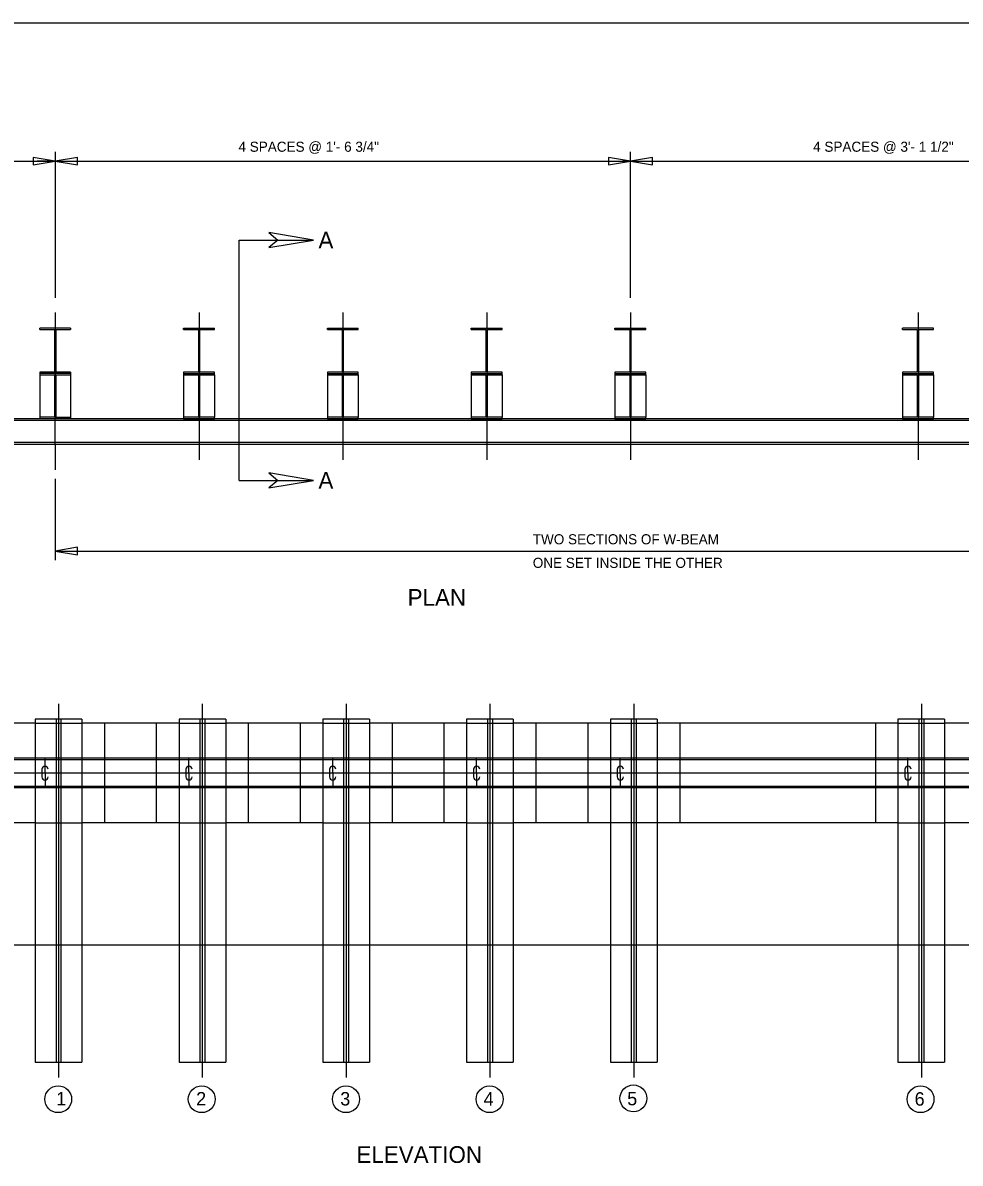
# Model space of a CAD drawing. Extents: x 809.7 to 842.4, y -901 to -880.3.
# Drawn here: x 819.41 to 829.59, y -892.79 to -880.4 of the extents above; entities that cross this region are included whole.
import ezdxf

# ---------------------------------------------------------------- set-up
doc = ezdxf.new("R2010")
doc.units = 0
for name, color, linetype in [('DIMENSION LINE', 7, 'Continuous'), ('EDGE OF PAVEMENT', 7, 'Continuous'), ('HIDDEN LINE', 7, 'Continuous'), ('OBJECT LINE', 7, 'Continuous'), ('REBAR', 7, 'Continuous'), ('STRUCTURES CENTERLINE', 7, 'Continuous'), ('STRUCTURES TEXT', 7, 'Continuous')]:
    doc.layers.add(name, color=color, linetype=linetype)

msp = doc.modelspace()

# ---------------------------------------------------------------- linework, layer by layer
at = {"layer": 'DIMENSION LINE'}
for p, q in [((819.76, -881.801), (819.76, -883.385)), ((826.01, -883.385), (826.01, -881.801)), ((813.51, -881.9), (819.76, -881.9)), ((819.76, -881.9), (826.01, -881.9)), ((826.01, -881.9), (832.26, -881.9)), ((819.76, -885.352), (819.76, -886.236)), ((819.76, -886.137), (832.26, -886.137)), ((819.616, -888.508), (819.616, -888.591)), ((821.179, -888.508), (821.179, -888.591)), ((822.741, -888.508), (822.741, -888.591)), ((824.304, -888.508), (824.304, -888.591)), ((825.866, -888.508), (825.866, -888.591)), ((828.991, -888.508), (828.991, -888.591))]:
    msp.add_line(p, q, dxfattribs=at)
for centre, start, end in [((819.65, -888.508), 360, 180), ((821.213, -888.508), 360, 180), ((822.775, -888.508), 360, 180), ((824.338, -888.508), 360, 180), ((825.9, -888.508), 360, 180), ((829.025, -888.508), 360, 180), ((819.65, -888.591), 180, 0), ((821.213, -888.591), 180, 0), ((822.775, -888.591), 180, 0), ((824.338, -888.591), 180, 0), ((825.9, -888.591), 180, 0), ((829.025, -888.591), 180, 0)]:
    msp.add_arc(centre, 0.0339, start, end, dxfattribs=at)
at = {"layer": 'EDGE OF PAVEMENT'}
for points in [[(819.52, -881.94), (819.76, -881.9), (819.52, -881.86)], [(820.001, -881.86), (819.76, -881.9), (820.001, -881.94)], [(825.77, -881.94), (826.01, -881.9), (825.77, -881.86)], [(826.251, -881.86), (826.01, -881.9), (826.251, -881.94)], [(820.001, -886.096), (819.76, -886.137), (820.001, -886.177)]]:
    msp.add_lwpolyline(points, close=True, dxfattribs=at)
for points in [[(819.76, -881.9), (819.564, -881.9)], [(819.76, -881.9), (819.872, -881.9)], [(826.01, -881.9), (825.927, -881.9)], [(826.046, -881.9), (826.041, -881.9)], [(826.046, -881.9), (826.12, -881.9)], [(819.76, -886.137), (819.867, -886.137)], [(819.76, -886.137), (819.822, -886.137)]]:
    msp.add_lwpolyline(points, dxfattribs=at)
for centre in [(819.792, -892.093), (821.352, -892.093), (822.919, -892.093), (824.48, -892.093), (826.042, -892.084), (829.162, -892.093)]:
    msp.add_circle(centre, 0.146, dxfattribs=at)
at = {"layer": 'HIDDEN LINE'}
for p, q in [((819.76, -884.978), (819.76, -884.701)), ((830.637, -884.958), (816.236, -884.958)), ((820.049, -887.964), (819.542, -887.964)), ((819.542, -887.964), (819.542, -890.417)), ((820.049, -887.964), (819.542, -887.964)), ((819.542, -887.964), (819.542, -890.417)), ((820.049, -887.964), (819.542, -887.964)), ((819.542, -887.964), (819.542, -890.417)), ((820.049, -887.964), (819.542, -887.964)), ((819.542, -887.964), (819.542, -890.417)), ((819.542, -888.006), (820.049, -888.006)), ((819.769, -887.964), (819.769, -891.69)), ((819.822, -887.964), (819.822, -891.69)), ((820.049, -887.964), (820.049, -890.417)), ((820.049, -887.964), (820.049, -890.417)), ((820.049, -887.964), (820.049, -890.417)), ((820.049, -887.964), (820.049, -890.417)), ((820.858, -888.006), (820.858, -889.089)), ((821.612, -887.964), (821.105, -887.964)), ((821.105, -887.964), (821.105, -890.417)), ((821.612, -887.964), (821.105, -887.964)), ((821.105, -887.964), (821.105, -890.417)), ((821.612, -887.964), (821.105, -887.964)), ((821.105, -887.964), (821.105, -890.417)), ((821.612, -887.964), (821.105, -887.964)), ((821.105, -887.964), (821.105, -890.417)), ((821.612, -887.964), (821.105, -887.964)), ((821.105, -887.964), (821.105, -890.417)), ((821.612, -887.964), (821.105, -887.964)), ((821.105, -887.964), (821.105, -890.417)), ((821.612, -887.964), (821.105, -887.964)), ((821.105, -887.964), (821.105, -890.417)), ((821.612, -887.964), (821.105, -887.964)), ((821.105, -887.964), (821.105, -890.417)), ((821.105, -888.006), (821.612, -888.006)), ((821.332, -887.964), (821.332, -891.69)), ((821.385, -887.964), (821.385, -891.69)), ((821.612, -887.964), (821.612, -890.417)), ((821.612, -887.964), (821.612, -890.417)), ((821.612, -887.964), (821.612, -890.417)), ((821.612, -887.964), (821.612, -890.417)), ((821.612, -887.964), (821.612, -890.417)), ((821.612, -887.964), (821.612, -890.417)), ((821.612, -887.964), (821.612, -890.417)), ((821.612, -887.964), (821.612, -890.417)), ((822.421, -888.006), (822.421, -889.089)), ((823.174, -887.964), (822.667, -887.964)), ((822.667, -887.964), (822.667, -890.417)), ((823.174, -887.964), (822.667, -887.964)), ((822.667, -887.964), (822.667, -890.417)), ((823.174, -887.964), (822.667, -887.964)), ((822.667, -887.964), (822.667, -890.417)), ((823.174, -887.964), (822.667, -887.964)), ((822.667, -887.964), (822.667, -890.417)), ((823.174, -887.964), (822.667, -887.964)), ((822.667, -887.964), (822.667, -890.417)), ((823.174, -887.964), (822.667, -887.964)), ((822.667, -887.964), (822.667, -890.417)), ((823.174, -887.964), (822.667, -887.964)), ((822.667, -887.964), (822.667, -890.417)), ((823.174, -887.964), (822.667, -887.964)), ((822.667, -887.964), (822.667, -890.417)), ((822.667, -888.006), (823.174, -888.006)), ((822.894, -887.964), (822.894, -891.69)), ((822.947, -887.964), (822.947, -891.69)), ((823.174, -887.964), (823.174, -890.417)), ((823.174, -887.964), (823.174, -890.417)), ((823.174, -887.964), (823.174, -890.417)), ((823.174, -887.964), (823.174, -890.417)), ((823.174, -887.964), (823.174, -890.417)), ((823.174, -887.964), (823.174, -890.417)), ((823.174, -887.964), (823.174, -890.417)), ((823.174, -887.964), (823.174, -890.417)), ((823.983, -888.006), (823.983, -889.089)), ((824.737, -887.964), (824.23, -887.964)), ((824.23, -887.964), (824.23, -890.417)), ((824.737, -887.964), (824.23, -887.964)), ((824.23, -887.964), (824.23, -890.417)), ((824.737, -887.964), (824.23, -887.964)), ((824.23, -887.964), (824.23, -890.417)), ((824.737, -887.964), (824.23, -887.964)), ((824.23, -887.964), (824.23, -890.417)), ((824.737, -887.964), (824.23, -887.964)), ((824.23, -887.964), (824.23, -890.417)), ((824.737, -887.964), (824.23, -887.964)), ((824.23, -887.964), (824.23, -890.417)), ((824.737, -887.964), (824.23, -887.964)), ((824.23, -887.964), (824.23, -890.417)), ((824.737, -887.964), (824.23, -887.964)), ((824.23, -887.964), (824.23, -890.417)), ((824.23, -888.006), (824.737, -888.006)), ((824.457, -887.964), (824.457, -891.69)), ((824.51, -887.964), (824.51, -891.69)), ((824.737, -887.964), (824.737, -890.417)), ((824.737, -887.964), (824.737, -890.417)), ((824.737, -887.964), (824.737, -890.417)), ((824.737, -887.964), (824.737, -890.417)), ((824.737, -887.964), (824.737, -890.417)), ((824.737, -887.964), (824.737, -890.417)), ((824.737, -887.964), (824.737, -890.417)), ((824.737, -887.964), (824.737, -890.417)), ((825.546, -888.006), (825.546, -889.089)), ((826.299, -887.964), (825.792, -887.964)), ((825.792, -887.964), (825.792, -890.417)), ((826.299, -887.964), (825.792, -887.964)), ((825.792, -887.964), (825.792, -890.417)), ((826.299, -887.964), (825.792, -887.964)), ((825.792, -887.964), (825.792, -890.417)), ((826.299, -887.964), (825.792, -887.964)), ((825.792, -887.964), (825.792, -890.417)), ((826.299, -887.964), (825.792, -887.964)), ((825.792, -887.964), (825.792, -890.417)), ((826.299, -887.964), (825.792, -887.964)), ((825.792, -887.964), (825.792, -890.417)), ((826.299, -887.964), (825.792, -887.964)), ((825.792, -887.964), (825.792, -890.417)), ((826.299, -887.964), (825.792, -887.964)), ((825.792, -887.964), (825.792, -890.417)), ((825.792, -888.006), (826.299, -888.006)), ((826.019, -887.964), (826.019, -891.69)), ((826.072, -887.964), (826.072, -891.69)), ((826.299, -887.964), (826.299, -890.417)), ((826.299, -887.964), (826.299, -890.417)), ((826.299, -887.964), (826.299, -890.417)), ((826.299, -887.964), (826.299, -890.417)), ((826.299, -887.964), (826.299, -890.417)), ((826.299, -887.964), (826.299, -890.417)), ((826.299, -887.964), (826.299, -890.417)), ((826.299, -887.964), (826.299, -890.417)), ((828.671, -888.006), (828.671, -889.089)), ((829.424, -887.964), (828.917, -887.964)), ((828.917, -887.964), (828.917, -890.417)), ((829.424, -887.964), (828.917, -887.964)), ((828.917, -887.964), (828.917, -890.417)), ((829.424, -887.964), (828.917, -887.964)), ((828.917, -887.964), (828.917, -890.417)), ((829.424, -887.964), (828.917, -887.964)), ((828.917, -887.964), (828.917, -890.417)), ((829.424, -887.964), (828.917, -887.964)), ((828.917, -887.964), (828.917, -890.417)), ((829.424, -887.964), (828.917, -887.964)), ((828.917, -887.964), (828.917, -890.417)), ((829.424, -887.964), (828.917, -887.964)), ((828.917, -887.964), (828.917, -890.417)), ((829.424, -887.964), (828.917, -887.964)), ((828.917, -887.964), (828.917, -890.417)), ((829.424, -887.964), (828.917, -887.964)), ((828.917, -887.964), (828.917, -890.417)), ((829.424, -887.964), (828.917, -887.964)), ((828.917, -887.964), (828.917, -890.417)), ((829.424, -887.964), (828.917, -887.964)), ((828.917, -887.964), (828.917, -890.417)), ((829.424, -887.964), (828.917, -887.964)), ((828.917, -887.964), (828.917, -890.417)), ((829.424, -887.964), (828.917, -887.964)), ((828.917, -887.964), (828.917, -890.417)), ((829.424, -887.964), (828.917, -887.964)), ((828.917, -887.964), (828.917, -890.417)), ((829.424, -887.964), (828.917, -887.964)), ((828.917, -887.964), (828.917, -890.417)), ((829.424, -887.964), (828.917, -887.964)), ((828.917, -887.964), (828.917, -890.417)), ((828.917, -888.006), (829.424, -888.006)), ((829.144, -887.964), (829.144, -891.69)), ((829.197, -887.964), (829.197, -891.69)), ((829.424, -887.964), (829.424, -890.417)), ((829.424, -887.964), (829.424, -890.417)), ((829.424, -887.964), (829.424, -890.417)), ((829.424, -887.964), (829.424, -890.417)), ((829.424, -887.964), (829.424, -890.417)), ((829.424, -887.964), (829.424, -890.417)), ((829.424, -887.964), (829.424, -890.417)), ((829.424, -887.964), (829.424, -890.417)), ((829.424, -887.964), (829.424, -890.417)), ((829.424, -887.964), (829.424, -890.417)), ((829.424, -887.964), (829.424, -890.417)), ((829.424, -887.964), (829.424, -890.417)), ((829.424, -887.964), (829.424, -890.417)), ((829.424, -887.964), (829.424, -890.417)), ((829.424, -887.964), (829.424, -890.417)), ((829.424, -887.964), (829.424, -890.417)), ((834.183, -888.389), (816.316, -888.389)), ((834.183, -888.404), (816.316, -888.404)), ((834.183, -888.694), (816.316, -888.694)), ((834.183, -888.71), (816.316, -888.71)), ((819.542, -889.089), (820.049, -889.089)), ((821.105, -889.089), (821.612, -889.089)), ((822.667, -889.089), (823.174, -889.089)), ((824.23, -889.089), (824.737, -889.089)), ((826.299, -889.089), (825.792, -889.089)), ((828.917, -889.089), (829.424, -889.089)), ((819.542, -890.417), (819.542, -891.69)), ((820.049, -890.417), (820.049, -891.69)), ((821.105, -890.417), (821.105, -891.69)), ((821.612, -890.417), (821.612, -891.69)), ((822.667, -890.417), (822.667, -891.69)), ((823.174, -890.417), (823.174, -891.69)), ((824.23, -890.417), (824.23, -891.69)), ((824.737, -890.417), (824.737, -891.69)), ((825.792, -890.417), (825.792, -891.69)), ((826.299, -890.417), (826.299, -891.69)), ((828.917, -890.417), (828.917, -891.69)), ((829.424, -890.417), (829.424, -891.69)), ((819.542, -891.69), (820.049, -891.69)), ((821.105, -891.69), (821.612, -891.69)), ((822.667, -891.69), (823.174, -891.69)), ((824.23, -891.69), (824.737, -891.69)), ((825.792, -891.69), (826.299, -891.69)), ((828.917, -891.69), (829.424, -891.69))]:
    msp.add_line(p, q, dxfattribs=at)
at = {"layer": 'OBJECT LINE'}
for p, q in [((819.594, -883.73), (819.594, -883.714)), ((819.927, -883.714), (819.927, -883.73)), ((821.155, -883.73), (821.155, -883.714)), ((821.155, -883.714), (821.49, -883.714)), ((822.717, -883.73), (822.717, -883.714)), ((822.717, -883.714), (823.053, -883.714)), ((824.28, -883.73), (824.28, -883.714)), ((824.28, -883.714), (824.615, -883.714)), ((824.615, -883.73), (824.615, -883.714)), ((825.842, -883.73), (825.842, -883.714)), ((825.842, -883.714), (826.178, -883.714)), ((826.178, -883.73), (826.178, -883.714)), ((828.967, -883.73), (828.967, -883.714)), ((819.594, -884.192), (819.594, -884.701)), ((819.927, -884.192), (819.927, -884.701)), ((821.155, -884.215), (821.155, -884.684)), ((821.49, -884.223), (821.49, -884.684)), ((822.717, -884.215), (822.717, -884.684)), ((823.053, -884.223), (823.053, -884.684)), ((824.28, -884.215), (824.28, -884.684)), ((824.615, -884.223), (824.615, -884.684)), ((825.842, -884.215), (825.842, -884.684)), ((826.178, -884.223), (826.178, -884.684)), ((828.967, -884.215), (828.967, -884.684)), ((829.303, -884.223), (829.303, -884.684)), ((830.637, -884.701), (816.236, -884.701)), ((822.502, -884.72), (816.236, -884.72)), ((819.769, -884.684), (819.927, -884.684)), ((821.155, -884.684), (821.155, -884.701)), ((830.637, -884.72), (822.502, -884.72)), ((822.717, -884.684), (822.717, -884.701)), ((824.28, -884.684), (824.28, -884.701)), ((825.842, -884.684), (825.842, -884.701)), ((828.967, -884.684), (828.967, -884.701)), ((830.683, -884.978), (816.236, -884.978)), ((819.542, -888.006), (816.316, -888.006)), ((821.105, -888.006), (820.049, -888.006)), ((820.296, -888.006), (820.296, -889.089)), ((822.667, -888.006), (821.612, -888.006)), ((821.858, -888.006), (821.858, -889.089)), ((824.23, -888.006), (823.174, -888.006)), ((823.421, -888.006), (823.421, -889.089)), ((825.792, -888.006), (824.737, -888.006)), ((824.983, -888.006), (824.983, -889.089)), ((828.917, -888.006), (826.299, -888.006)), ((826.546, -888.006), (826.546, -889.089)), ((830.657, -888.006), (829.424, -888.006)), ((819.542, -889.089), (816.316, -889.089)), ((821.105, -889.089), (820.049, -889.089)), ((822.667, -889.089), (821.612, -889.089)), ((824.23, -889.089), (823.174, -889.089)), ((825.792, -889.089), (824.737, -889.089)), ((828.917, -889.089), (826.299, -889.089)), ((830.637, -889.089), (829.424, -889.089)), ((816.316, -890.417), (830.637, -890.417))]:
    msp.add_line(p, q, dxfattribs=at)
for points in [[(819.927, -883.714), (819.594, -883.714)], [(819.594, -883.73), (819.752, -883.73)], [(819.752, -883.73), (819.752, -884.192), (819.594, -884.192)], [(819.769, -883.73), (819.927, -883.73)], [(819.927, -884.192), (819.769, -884.192), (819.769, -883.73)], [(821.155, -884.207), (821.49, -884.207), (821.49, -884.192), (821.331, -884.192), (821.331, -883.73)], [(821.315, -883.73), (821.315, -884.192), (821.155, -884.192), (821.155, -884.207)], [(821.155, -883.73), (821.315, -883.73)], [(821.331, -883.73), (821.49, -883.73), (821.49, -883.714)], [(822.717, -884.207), (823.053, -884.207), (823.053, -884.192), (822.894, -884.192), (822.894, -883.73)], [(822.877, -883.73), (822.877, -884.192), (822.717, -884.192), (822.717, -884.207)], [(822.717, -883.73), (822.877, -883.73)], [(822.894, -883.73), (823.053, -883.73), (823.053, -883.714)], [(824.28, -884.207), (824.615, -884.207), (824.615, -884.192), (824.456, -884.192), (824.456, -883.73)], [(824.28, -883.73), (824.44, -883.73)], [(824.456, -883.73), (824.615, -883.73)], [(825.842, -884.207), (826.178, -884.207), (826.178, -884.192), (826.019, -884.192), (826.019, -883.73)], [(826.002, -883.73), (826.002, -884.192), (825.842, -884.192), (825.842, -884.207)], [(825.842, -883.73), (826.002, -883.73)], [(826.019, -883.73), (826.178, -883.73)], [(829.144, -883.73), (829.303, -883.73), (829.303, -883.714), (828.967, -883.714)], [(829.127, -883.73), (829.127, -884.192), (828.967, -884.192), (828.967, -884.207)], [(828.967, -883.73), (829.127, -883.73)], [(828.967, -884.207), (829.303, -884.207), (829.303, -884.192), (829.144, -884.192), (829.144, -883.73)], [(819.927, -884.207), (819.594, -884.207)], [(819.594, -884.223), (819.752, -884.223), (819.752, -884.684)], [(819.769, -884.684), (819.769, -884.223), (819.927, -884.223)], [(821.155, -884.207), (821.155, -884.223), (821.315, -884.223), (821.315, -884.684)], [(821.331, -884.684), (821.331, -884.223), (821.49, -884.223), (821.49, -884.207)], [(822.717, -884.207), (822.717, -884.223), (822.877, -884.223), (822.877, -884.684)], [(822.894, -884.684), (822.894, -884.223), (823.053, -884.223), (823.053, -884.207)], [(824.28, -884.207), (824.28, -884.223), (824.44, -884.223), (824.44, -884.684)], [(824.456, -884.684), (824.456, -884.223), (824.615, -884.223), (824.615, -884.207)], [(825.842, -884.207), (825.842, -884.223), (826.002, -884.223), (826.002, -884.684)], [(826.019, -884.684), (826.019, -884.223), (826.178, -884.223), (826.178, -884.207)], [(828.967, -884.207), (828.967, -884.223), (829.127, -884.223), (829.127, -884.684)], [(829.144, -884.684), (829.144, -884.223), (829.303, -884.223), (829.303, -884.207)], [(819.752, -884.684), (819.594, -884.684)], [(821.155, -884.701), (821.49, -884.701), (821.49, -884.684), (821.331, -884.684)], [(821.315, -884.684), (821.155, -884.684)], [(822.717, -884.701), (823.053, -884.701), (823.053, -884.684), (822.894, -884.684)], [(822.877, -884.684), (822.717, -884.684)], [(824.28, -884.701), (824.615, -884.701), (824.615, -884.684), (824.456, -884.684)], [(824.44, -884.684), (824.28, -884.684)], [(825.842, -884.701), (826.178, -884.701), (826.178, -884.684), (826.019, -884.684)], [(826.002, -884.684), (825.842, -884.684)], [(828.967, -884.701), (829.303, -884.701), (829.303, -884.684), (829.144, -884.684)], [(829.127, -884.684), (828.967, -884.684)]]:
    msp.add_lwpolyline(points, dxfattribs=at)
at = {"layer": 'REBAR'}
msp.add_line((811.186, -880.398), (842.1, -880.399), dxfattribs=at)
at = {"layer": 'STRUCTURES CENTERLINE'}
for p, q in [((821.759, -882.758), (822.565, -882.758)), ((821.759, -885.369), (821.759, -882.758)), ((819.76, -883.547), (819.76, -884.701)), ((821.323, -883.547), (821.323, -885.145)), ((822.885, -883.547), (822.885, -885.145)), ((824.448, -883.547), (824.448, -885.145)), ((826.01, -883.547), (826.01, -885.145)), ((829.135, -883.547), (829.135, -885.145)), ((819.76, -884.978), (819.76, -885.253)), ((821.759, -885.369), (822.565, -885.369)), ((819.796, -887.797), (819.796, -891.857)), ((821.358, -887.797), (821.358, -891.857)), ((822.921, -887.797), (822.921, -891.857)), ((824.483, -887.797), (824.483, -891.857)), ((826.046, -887.797), (826.046, -891.857)), ((829.171, -887.797), (829.171, -891.857)), ((819.65, -888.549), (819.65, -888.385)), ((821.213, -888.549), (821.213, -888.385)), ((822.775, -888.549), (822.775, -888.385)), ((824.338, -888.549), (824.338, -888.385)), ((825.9, -888.549), (825.9, -888.385)), ((829.025, -888.549), (829.025, -888.385)), ((834.271, -888.549), (816.316, -888.549)), ((819.65, -888.549), (819.65, -888.713)), ((821.213, -888.549), (821.213, -888.713)), ((822.775, -888.549), (822.775, -888.713)), ((824.338, -888.549), (824.338, -888.713)), ((825.9, -888.549), (825.9, -888.713)), ((829.025, -888.549), (829.025, -888.713))]:
    msp.add_line(p, q, dxfattribs=at)
for points in [[(822.565, -882.758), (822.082, -882.677), (822.179, -882.758), (822.082, -882.839)], [(822.565, -885.369), (822.082, -885.289), (822.179, -885.369), (822.082, -885.45)]]:
    msp.add_lwpolyline(points, close=True, dxfattribs=at)
at = {"layer": 'STRUCTURES TEXT'}
msp.add_lwpolyline([(824.44, -883.73), (824.44, -884.192), (824.28, -884.192), (824.28, -884.207)], dxfattribs=at)

# ---------------------------------------------------------------- texts
for s, height, p in [('4 SPACES @ 1\'- 6 3/4"', 0.10979, (821.751, -881.799)), ('4 SPACES @ 3\'- 1 1/2"', 0.10979, (827.995, -881.799)), ('A', 0.182, (822.62, -882.849)), ('A', 0.182, (822.62, -885.46)), ('TWO SECTIONS OF W-BEAM', 0.10979, (824.949, -886.064)), ('ONE SET INSIDE THE OTHER', 0.10979, (824.949, -886.32)), ('PLAN', 0.1818, (823.589, -886.732)), ('1', 0.146, (819.77, -892.16)), ('2', 0.146, (821.291, -892.161)), ('3', 0.146, (822.857, -892.161)), ('4', 0.146, (824.415, -892.162)), ('5', 0.146, (825.975, -892.159)), ('6', 0.146, (829.098, -892.163)), ('ELEVATION', 0.1818, (823.033, -892.785))]:
    msp.add_text(s, height=height, dxfattribs=at).set_placement(p)

doc.saveas('drawing.dxf')
